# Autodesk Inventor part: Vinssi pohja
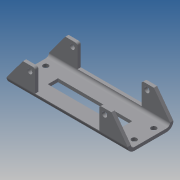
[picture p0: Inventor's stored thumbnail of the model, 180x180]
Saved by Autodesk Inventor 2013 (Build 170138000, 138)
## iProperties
Created: 2013-08
Part Number: Vinssi pohja
Material: Generic
Document SubType Name: Sheet Metal
Designer: Reko Tuppurainen
Density: 1 g/cm^3
Sheet Metal Rule: Default_mm
Flat Pattern Width: 22.4191 cm
Flat Pattern Length: 29.7 cm
Flat Pattern Area: 665.848 cm^2
Sheet Metal Width: 224,191 mm
Sheet Metal Length: 297,000 mm
Sheet Metal Area: 66584,771 mm^2
Author: Reko Tuppurainen
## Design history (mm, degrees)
node "Face1"
  sketch "Sketch1"
    geometry: L1 (-148.5, 56)-(148.5, 56); L2 (148.5, 56)-(148.5, -56); L3 (148.5, -56)-(-148.5, -56); L4 (-148.5, -56)-(-148.5, 56); 2 further points
    constraints: 8 end point, 2 parallel, 1 coincident, 1 horizontal, 1 perpendicular
    dimensions: "d0" = 297 distance of L2.end L3.end; "d1" = 112 distance of L1.end L2.end
node "Flange1"
sketch "Sketch3"
  geometry: L1 (-91, -12.5)-(91, -12.5); L2 (91, -12.5)-(91, 12.5); L3 (91, 12.5)-(-91, 12.5); L4 (-91, 12.5)-(-91, -12.5); L5 (-91, -12.5)-(91, 12.5); 3 further points
  constraints: 10 end point, 2 coincident, 2 parallel, 1 horizontal, 1 midpoint, 1 perpendicular
  dimensions: "d15" = 182 distance of L3.end L2.end; "d16" = 25 distance of L2.end L1.end
cut "Cut1" sketch "Sketch3" dims "d17" = 8 (= Thickness), "d18" = 0
sketch "Sketch4"
  geometry: L1 (-148.5, -40)-(148.5, -40) reference; L2 (148.5, 40)-(148.5, -40) reference; L3 (148.5, 40)-(-148.5, 40) reference; L4 (-148.5, -40)-(-148.5, 40) reference; C1 r 6.5 at (-132.5, 24); C2 r 6.5 at (-132.5, -24); C3 r 6.5 at (132.5, 24); C4 r 6.5 at (132.5, -24); 1 further point
  constraints: 4 centre point
  dimensions: "d19" = 13 diameter of C1; "d20" = 13 diameter of C2; "d21" = 13 diameter of C3; "d22" = 13 diameter of C4; "d23" = 16 distance from line of C1.centre L3; "d24" = 16 distance from line of L4 C1.centre; "d25" = 16 distance from line of L4 C2.centre; "d26" = 16 distance from line of L1 C2.centre; "d27" = 16 distance from line of L1 C4.centre; "d28" = 16 distance from line of L2 C4.centre; "d29" = 16 distance from line of L2 C3.centre; "d30" = 16 distance from line of L3 C3.centre
cut "Cut2" sketch "Sketch4" dims "d31" = 8 (= Thickness), "d32" = 0
sketch "Sketch5"
  geometry: L1 (297, 54)-(0, 54) reference; L2 (0, 0)-(0, 54) reference; L3 (297, 0)-(0, 0) reference; L4 (297, 54)-(297, 0) reference; L5 (70, 0)-(70, 54); L6 (227, 0)-(227, 54); 1 further point
  constraints: 4 end point, 4 point on line, 2 perpendicular
  dimensions: "d33" = 70 distance between parallel lines of L2 L5; "d34" = 70 distance between parallel lines of L4 L6
cut "Cut3" sketch "Sketch5" dims "d35" = 8 (= Thickness), "d36" = 0
sketch "Sketch6"
  geometry: L1 (0, 0)-(0, 54) reference; L2 (70, 0)-(0, 0) reference; L3 (0, 0)-(40, 0); L4 (40, 0)-(0, 54); 1 further point
  constraints: 4 end point, 1 point on line
  dimensions: "d37" = 40 distance of L1.start L3.end
cut "Cut4" sketch "Sketch6" dims "d38" = 8 (= Thickness), "d39" = 0
sketch "Sketch7"
  geometry: L1 (0, 0)-(-70, 0) reference; L2 (0, 54)-(0, 0) reference; L3 (0, 0)-(-40, 0); L4 (-40, 0)-(0, 54); 1 further point
  constraints: 4 end point, 1 point on line
  dimensions: "d40" = 40 distance of L1.start L3.end
cut "Cut5" sketch "Sketch7" dims "d41" = 8 (= Thickness), "d42" = 0
feature "Corner Round1" dims "d43" = 6
sketch "Sketch8"
  geometry: L1 (70, -48)-(70, 0) reference; L2 (64, -54)-(40, -54) reference; C1 r 6 at (57, -41); 1 further point
  constraints: 1 centre point
  dimensions: "d44" = 12 diameter of C1; "d45" = 13 distance from line of C1.centre L2; "d46" = 13 distance from line of L1 C1.centre
cut "Cut6" sketch "Sketch8" dims "d47" = 8 (= Thickness), "d48" = 0
sketch "Sketch9"
  geometry: L1 (30, -54)-(6, -54) reference; L2 (0, 0)-(0, -48) reference; C1 r 6.5 at (13, -41); 1 further point
  constraints: 1 centre point
  dimensions: "d49" = 13 diameter of C1; "d50" = 13 distance from line of L2 C1.centre; "d51" = 13 distance from line of C1.centre L1
cut "Cut7" sketch "Sketch9" dims "d52" = 8 (= Thickness), "d53" = 0
body "Solid1"
face "Plate1" dims "Thickness" = 8 (derived)
sketch "Sketch2"
  geometry: L1 through (-148.5, 0) direction (1, 0); L2 through (0, 35) direction (0, 1); L3 (0, 70)-(-297, 70); L4 (-297, 70)-(-297, 0)
  constraints: 6 end point, 1 horizontal, 1 perpendicular, 1 vertical
face "Plate2" dims "d3" = 8 (= BendReliefWidth), "d4" = 4 (= BendReliefDepth), "d5" = 16 (= MinimumRemnant), "d6" = 8 (= BendRadius), "d7" = 70, "d8" = 90 deg, "d9" = 8 (= BendRadius), "d10" = 32 (= CornerReliefSize), "d11" = 8 (= GapSize), "d12" = 8 (= JacobiRadiusSize), "SeamGap" = 0.01, "Thickness" = 8 (derived)
bend "Bend1" dims "d3" = 8 (= BendReliefWidth), "d4" = 4 (= BendReliefDepth), "d5" = 16 (= MinimumRemnant), "d6" = 8 (= BendRadius), "d7" = 70, "d8" = 90 deg, "d9" = 8 (= BendRadius), "SeamGap" = 0.01, "Thickness" = 8 (derived)
feature "Corner1" dims "d7" = 70, "d8" = 90 deg, "d10" = 32 (= CornerReliefSize), "d11" = 8 (= GapSize), "d12" = 8 (= JacobiRadiusSize)
feature "Definition1"
other parameters: "BendRadius" = 8 (= Thickness), "BendReliefWidth" = 8 (= Thickness), "BendReliefDepth" = 4 (= 0.5 x Thickness), "CornerReliefSize" = 32 (= 4 x Thickness), "MinimumRemnant" = 16 (= 2 x Thickness), "TransitionRadius" = 8 (= BendRadius), "JacobiRadiusSize" = 8 (= BendRadius), "GapSize" = 8 (= Thickness), "d2" = 8 (= BendRadius), "BendRadius" = 8, "BendReliefDepth" = 4, "BendReliefWidth" = 8, "CornerReliefSize" = 32, "GapSize" = 8, "JacobiRadiusSize" = 8, "MinimumRemnant" = 16, "Thickness" = 8, "TransitionRadius" = 8
